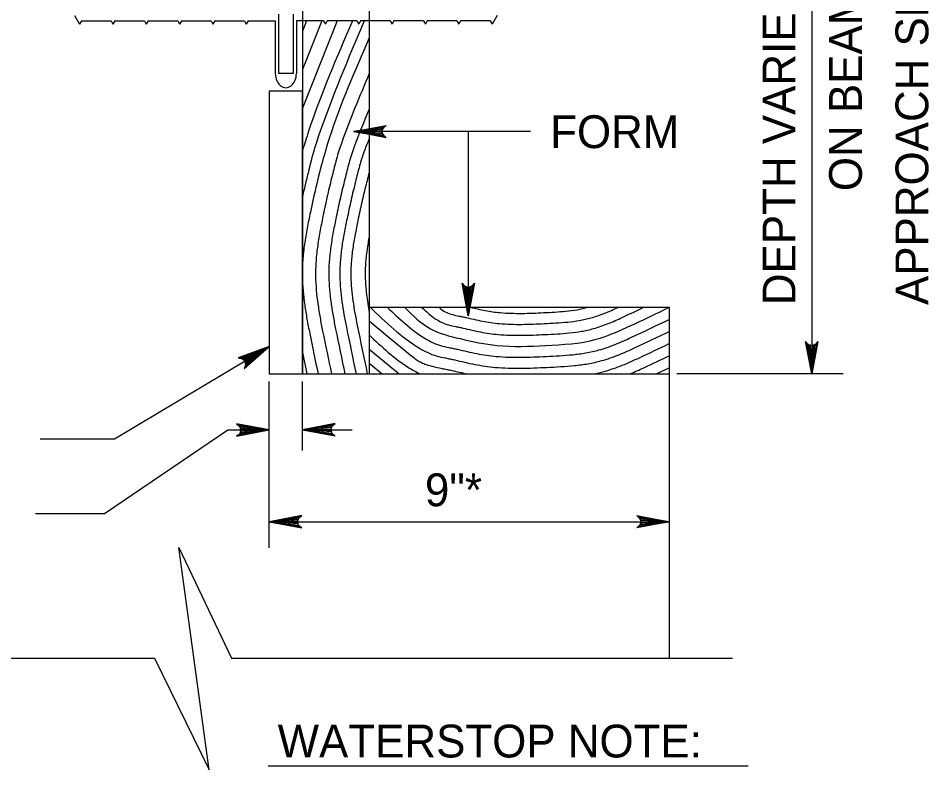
# Model space of a CAD drawing. Extents: x 636530 to 644067, y 294168 to 299122.
# Drawn here: x 636586.8 to 636670, y 298165.7 to 298234.3 of the extents above; entities that cross this region are included whole.
import ezdxf

# ---------------------------------------------------------------- set-up
doc = ezdxf.new("R2010")
doc.units = 0
doc.layers.add('1', color=7, linetype='Continuous')

msp = doc.modelspace()

# ---------------------------------------------------------------- linework, layer by layer
at = {"layer": '1'}
for p, q in [((636618.88, 298266.856), (636618.88, 298201.834)), ((636659.328, 298266.856), (636659.328, 298201.834)), ((636612.784, 298245.46), (636612.784, 298201.834)), ((636610.598, 298234.706), (636610.598, 298229.277)), ((636611.921, 298234.706), (636611.921, 298229.277)), ((636591.955, 298234.598), (636592.405, 298233.79)), ((636592.572, 298234.09), (636592.405, 298233.79)), ((636592.572, 298234.09), (636595.285, 298234.09)), ((636595.285, 298234.09), (636595.453, 298233.79)), ((636595.62, 298234.09), (636595.453, 298233.79)), ((636595.62, 298234.09), (636598.333, 298234.09)), ((636598.333, 298234.09), (636598.501, 298233.79)), ((636598.668, 298234.09), (636598.501, 298233.79)), ((636598.668, 298234.09), (636601.381, 298234.09)), ((636601.381, 298234.09), (636601.549, 298233.79)), ((636601.716, 298234.09), (636601.549, 298233.79)), ((636601.716, 298234.09), (636604.429, 298234.09)), ((636604.429, 298234.09), (636604.597, 298233.79)), ((636604.764, 298234.09), (636604.597, 298233.79)), ((636604.764, 298234.09), (636607.477, 298234.09)), ((636607.477, 298234.09), (636607.645, 298233.79)), ((636607.812, 298234.09), (636607.645, 298233.79)), ((636607.812, 298234.09), (636610.298, 298234.09)), ((636610.298, 298234.09), (636610.298, 298229.277)), ((636612.221, 298234.09), (636612.221, 298229.277)), ((636614.707, 298234.09), (636612.221, 298234.09)), ((636613.148, 298234.09), (636612.784, 298233.174)), ((636614.547, 298234.09), (636612.784, 298229.656)), ((636615.946, 298234.09), (636612.784, 298226.138)), ((636614.707, 298234.09), (636614.875, 298233.79)), ((636615.042, 298234.09), (636614.875, 298233.79)), ((636617.755, 298234.09), (636615.042, 298234.09)), ((636617.755, 298234.09), (636617.923, 298233.79)), ((636618.09, 298234.09), (636617.923, 298233.79)), ((636620.803, 298234.09), (636618.09, 298234.09)), ((636620.803, 298234.09), (636620.971, 298233.79)), ((636621.138, 298234.09), (636620.971, 298233.79)), ((636623.851, 298234.09), (636621.138, 298234.09)), ((636623.851, 298234.09), (636624.019, 298233.79)), ((636624.186, 298234.09), (636624.019, 298233.79)), ((636626.899, 298234.09), (636624.186, 298234.09)), ((636626.899, 298234.09), (636627.067, 298233.79)), ((636627.234, 298234.09), (636627.067, 298233.79)), ((636629.947, 298234.09), (636627.234, 298234.09)), ((636629.947, 298234.09), (636630.115, 298233.79)), ((636630.565, 298234.598), (636630.115, 298233.79)), ((636611.921, 298229.277), (636610.598, 298229.277)), ((636609.736, 298227.667), (636609.736, 298201.834)), ((636633.627, 298223.984), (636617.457, 298223.984)), ((636627.94, 298223.984), (636627.94, 298207.156)), ((636618.88, 298207.93), (636646.312, 298207.93)), ((636646.312, 298207.93), (636646.312, 298201.834)), ((636595.59, 298195.919), (636609.736, 298204.343)), ((636618.88, 298204.107), (636621.631, 298201.834)), ((636612.784, 298203.789), (636613.188, 298201.834)), ((636618.88, 298202.81), (636620.061, 298201.834)), ((636645.122, 298201.834), (636646.312, 298202.397)), ((636609.736, 298201.834), (636646.312, 298201.834)), ((636646.312, 298201.834), (636646.312, 298175.875)), ((636662.191, 298201.834), (636646.991, 298201.834)), ((636609.736, 298185.954), (636609.736, 298201.154)), ((636612.784, 298194.844), (636612.784, 298201.154)), ((636594.695, 298189.095), (636605.952, 298196.722)), ((636605.952, 298196.722), (636609.736, 298196.722)), ((636612.784, 298196.722), (636617.326, 298196.722)), ((636588.805, 298195.919), (636595.59, 298195.919)), ((636588.363, 298189.095), (636594.695, 298189.095)), ((636609.736, 298188.331), (636646.312, 298188.331)), ((636557.946, 298175.875), (636599.254, 298175.875)), ((636606.289, 298175.875), (636652.095, 298175.875)), ((636609.636, 298166.029), (636653.514, 298166.029))]:
    msp.add_line(p, q, dxfattribs=at)
msp.add_lwpolyline([(636609.736, 298201.834), (636612.784, 298201.834), (636612.784, 298227.667), (636609.736, 298227.667)], close=True, dxfattribs=at)
for points in [[(636617.457, 298223.984), (636620.44, 298224.543), (636620.325, 298224.463), (636620.21, 298224.384), (636620.151, 298224.284), (636620.092, 298224.184), (636620.074, 298224.084), (636620.057, 298223.984), (636620.074, 298223.884), (636620.092, 298223.784), (636620.151, 298223.684), (636620.21, 298223.584), (636620.325, 298223.504), (636620.44, 298223.424), (636617.457, 298223.984), (636620.325, 298223.504), (636620.21, 298223.584), (636617.457, 298223.984), (636620.151, 298223.684), (636620.092, 298223.784), (636617.457, 298223.984), (636620.074, 298223.884), (636620.057, 298223.984), (636617.457, 298223.984), (636620.074, 298224.084), (636620.092, 298224.184), (636617.457, 298223.984), (636620.151, 298224.284), (636620.21, 298224.384), (636617.457, 298223.984), (636620.325, 298224.463)], [(636627.94, 298207.156), (636627.381, 298210.138), (636627.461, 298210.024), (636627.54, 298209.909), (636627.64, 298209.849), (636627.74, 298209.79), (636627.84, 298209.773), (636627.94, 298209.756), (636628.04, 298209.773), (636628.14, 298209.79), (636628.24, 298209.849), (636628.34, 298209.909), (636628.42, 298210.024), (636628.5, 298210.138), (636627.94, 298207.156), (636628.42, 298210.024), (636628.34, 298209.909), (636627.94, 298207.156), (636628.24, 298209.849), (636628.14, 298209.79), (636627.94, 298207.156), (636628.04, 298209.773), (636627.94, 298209.756), (636627.94, 298207.156), (636627.84, 298209.773), (636627.74, 298209.79), (636627.94, 298207.156), (636627.64, 298209.849), (636627.54, 298209.909), (636627.94, 298207.156), (636627.461, 298210.024)], [(636659.328, 298201.834), (636658.769, 298204.816), (636658.848, 298204.701), (636658.928, 298204.587), (636659.028, 298204.527), (636659.128, 298204.468), (636659.228, 298204.451), (636659.328, 298204.434), (636659.428, 298204.451), (636659.528, 298204.468), (636659.628, 298204.527), (636659.728, 298204.587), (636659.808, 298204.701), (636659.887, 298204.816), (636659.328, 298201.834), (636659.808, 298204.701), (636659.728, 298204.587), (636659.328, 298201.834), (636659.628, 298204.527), (636659.528, 298204.468), (636659.328, 298201.834), (636659.428, 298204.451), (636659.328, 298204.434), (636659.328, 298201.834), (636659.228, 298204.451), (636659.128, 298204.468), (636659.328, 298201.834), (636659.028, 298204.527), (636658.928, 298204.587), (636659.328, 298201.834), (636658.848, 298204.701)], [(636609.736, 298204.343), (636606.887, 298203.298), (636607.026, 298203.288), (636607.166, 298203.278), (636607.268, 298203.223), (636607.37, 298203.167), (636607.436, 298203.09), (636607.502, 298203.013), (636607.538, 298202.918), (636607.575, 298202.824), (636607.575, 298202.707), (636607.575, 298202.591), (636607.517, 298202.464), (636607.459, 298202.337), (636609.736, 298204.343), (636607.517, 298202.464), (636607.575, 298202.591), (636609.736, 298204.343), (636607.575, 298202.707), (636607.575, 298202.824), (636609.736, 298204.343), (636607.538, 298202.918), (636607.502, 298203.013), (636609.736, 298204.343), (636607.436, 298203.09), (636607.37, 298203.167), (636609.736, 298204.343), (636607.268, 298203.223), (636607.166, 298203.278), (636609.736, 298204.343), (636607.026, 298203.288)], [(636609.736, 298196.722), (636606.75, 298197.266), (636606.865, 298197.187), (636606.981, 298197.108), (636607.041, 298197.009), (636607.1, 298196.909), (636607.118, 298196.809), (636607.136, 298196.709), (636607.119, 298196.609), (636607.102, 298196.509), (636607.043, 298196.409), (636606.985, 298196.308), (636606.87, 298196.228), (636606.756, 298196.148), (636609.736, 298196.722), (636606.87, 298196.228), (636606.985, 298196.308), (636609.736, 298196.722), (636607.043, 298196.409), (636607.102, 298196.509), (636609.736, 298196.722), (636607.119, 298196.609), (636607.136, 298196.709), (636609.736, 298196.722), (636607.118, 298196.809), (636607.1, 298196.909), (636609.736, 298196.722), (636607.041, 298197.009), (636606.981, 298197.108), (636609.736, 298196.722), (636606.865, 298197.187)], [(636612.784, 298196.722), (636615.769, 298196.175), (636615.653, 298196.254), (636615.538, 298196.333), (636615.478, 298196.433), (636615.419, 298196.533), (636615.401, 298196.633), (636615.383, 298196.733), (636615.4, 298196.833), (636615.417, 298196.933), (636615.476, 298197.033), (636615.535, 298197.133), (636615.649, 298197.214), (636615.764, 298197.294), (636612.784, 298196.722), (636615.649, 298197.214), (636615.535, 298197.133), (636612.784, 298196.722), (636615.476, 298197.033), (636615.417, 298196.933), (636612.784, 298196.722), (636615.4, 298196.833), (636615.383, 298196.733), (636612.784, 298196.722), (636615.401, 298196.633), (636615.419, 298196.533), (636612.784, 298196.722), (636615.478, 298196.433), (636615.538, 298196.333), (636612.784, 298196.722), (636615.653, 298196.254)], [(636609.736, 298188.331), (636612.718, 298187.772), (636612.603, 298187.852), (636612.488, 298187.931), (636612.429, 298188.031), (636612.37, 298188.131), (636612.353, 298188.231), (636612.336, 298188.331), (636612.353, 298188.431), (636612.37, 298188.531), (636612.429, 298188.631), (636612.488, 298188.731), (636612.603, 298188.811), (636612.718, 298188.89), (636609.736, 298188.331), (636612.603, 298188.811), (636612.488, 298188.731), (636609.736, 298188.331), (636612.429, 298188.631), (636612.37, 298188.531), (636609.736, 298188.331), (636612.353, 298188.431), (636612.336, 298188.331), (636609.736, 298188.331), (636612.353, 298188.231), (636612.37, 298188.131), (636609.736, 298188.331), (636612.429, 298188.031), (636612.488, 298187.931), (636609.736, 298188.331), (636612.603, 298187.852)], [(636646.312, 298188.331), (636643.329, 298187.772), (636643.444, 298187.852), (636643.559, 298187.931), (636643.618, 298188.031), (636643.677, 298188.131), (636643.694, 298188.231), (636643.712, 298188.331), (636643.694, 298188.431), (636643.677, 298188.531), (636643.618, 298188.631), (636643.559, 298188.731), (636643.444, 298188.811), (636643.329, 298188.89), (636646.312, 298188.331), (636643.444, 298188.811), (636643.559, 298188.731), (636646.312, 298188.331), (636643.618, 298188.631), (636643.677, 298188.531), (636646.312, 298188.331), (636643.694, 298188.431), (636643.712, 298188.331), (636646.312, 298188.331), (636643.694, 298188.231), (636643.677, 298188.131), (636646.312, 298188.331), (636643.618, 298188.031), (636643.559, 298187.931), (636646.312, 298188.331), (636643.444, 298187.852)], [(636599.254, 298175.875), (636604.252, 298165.663), (636601.491, 298185.961), (636606.289, 298175.875)]]:
    msp.add_lwpolyline(points, dxfattribs=at)
msp.add_ellipse((636611.26, 298229.277), major_axis=(0, 1.283), ratio=0.75, start_param=1.570796, end_param=4.712389, dxfattribs=at)
for points in [[(636617.345, 298234.09), (636613.338, 298224.015), (636612.784, 298222.273)], [(636618.421, 298234.09), (636614.285, 298223.691), (636613.776, 298222.11), (636613.365, 298220.497), (636613.063, 298219.276), (636612.784, 298218.051)], [(636618.88, 298232.537), (636615.233, 298223.367), (636614.333, 298220.246), (636613.499, 298216.61), (636613.208, 298215.146), (636612.966, 298213.681), (636612.808, 298212.216), (636612.771, 298211.484), (636612.768, 298210.752), (636612.985, 298208.14), (636613.191, 298206.838), (636613.441, 298205.545), (636614.209, 298201.834)], [(636618.88, 298229.289), (636616.369, 298222.978), (636615.886, 298221.478), (636615.689, 298220.712), (636615.495, 298219.946), (636615.275, 298219.065), (636615.069, 298218.183), (636614.683, 298216.401), (636614.402, 298214.99), (636614.169, 298213.578), (636614.016, 298212.166), (636613.981, 298211.46), (636613.977, 298210.755), (636614.186, 298208.241), (636614.385, 298206.988), (636614.625, 298205.744), (636615.435, 298201.834)], [(636618.88, 298226.042), (636617.506, 298222.589), (636617.037, 298221.133), (636616.845, 298220.389), (636616.658, 298219.645), (636616.443, 298218.787), (636616.242, 298217.928), (636616.051, 298217.064), (636615.866, 298216.192), (636615.596, 298214.834), (636615.371, 298213.475), (636615.225, 298212.116), (636615.19, 298211.436), (636615.184, 298211.097), (636615.187, 298210.757), (636615.388, 298208.342), (636615.579, 298207.138), (636615.81, 298205.943), (636616.66, 298201.834)], [(636618.88, 298223.336), (636618.453, 298222.265), (636617.996, 298220.845), (636617.809, 298220.12), (636617.626, 298219.395), (636617.416, 298218.556), (636617.22, 298217.716), (636617.032, 298216.871), (636616.852, 298216.018), (636616.591, 298214.704), (636616.373, 298213.389), (636616.231, 298212.074), (636616.198, 298211.417), (636616.193, 298211.088), (636616.195, 298210.759), (636616.389, 298208.427), (636616.573, 298207.263), (636616.797, 298206.109), (636617.682, 298201.834)], [(636618.88, 298220.268), (636618.773, 298219.851), (636618.595, 298219.144), (636618.39, 298218.324), (636618.197, 298217.503), (636618.014, 298216.678), (636617.838, 298215.844), (636617.585, 298214.573), (636617.376, 298213.303), (636617.238, 298212.032), (636617.206, 298211.397), (636617.201, 298211.079), (636617.203, 298210.762), (636617.39, 298208.511), (636617.568, 298207.388), (636617.783, 298206.274), (636618.703, 298201.834)], [(636618.88, 298214.409), (636618.879, 298214.404), (636618.678, 298213.191), (636618.547, 298211.978), (636618.516, 298211.371), (636618.514, 298210.764), (636618.63, 298209.105), (636618.742, 298208.276), (636618.88, 298207.449)], [(636618.962, 298207.93), (636623.491, 298204.188), (636625.004, 298203.482), (636625.85, 298203.295), (636626.275, 298203.21), (636626.693, 298203.12), (636627.617, 298202.907), (636628.541, 298202.711), (636629.469, 298202.55), (636630.405, 298202.439), (636631.582, 298202.371), (636632.762, 298202.358), (636633.942, 298202.386), (636635.12, 298202.439), (636636.379, 298202.506), (636637.635, 298202.603), (636638.885, 298202.771), (636639.508, 298202.894), (636640.127, 298203.05), (636641.695, 298203.584), (636643.199, 298204.242), (636646.312, 298205.717)], [(636620.532, 298207.93), (636623.985, 298205.078), (636625.382, 298204.425), (636626.163, 298204.252), (636626.556, 298204.174), (636626.943, 298204.091), (636627.827, 298203.887), (636628.712, 298203.7), (636629.6, 298203.545), (636630.496, 298203.439), (636631.635, 298203.373), (636632.777, 298203.361), (636633.919, 298203.387), (636635.059, 298203.439), (636636.272, 298203.503), (636637.482, 298203.597), (636638.686, 298203.758), (636639.285, 298203.877), (636639.882, 298204.027), (636641.373, 298204.535), (636642.804, 298205.161), (636646.312, 298206.823)], [(636622.102, 298207.93), (636624.478, 298205.967), (636627.193, 298205.062), (636630.587, 298204.439), (636634.998, 298204.439), (636639.637, 298205.005), (636642.408, 298206.081), (636646.312, 298207.93)], [(636623.672, 298207.93), (636624.971, 298206.857), (636626.139, 298206.312), (636626.791, 298206.168), (636627.119, 298206.102), (636627.443, 298206.032), (636628.248, 298205.847), (636629.053, 298205.676), (636629.862, 298205.536), (636630.678, 298205.439), (636631.741, 298205.378), (636632.807, 298205.366), (636633.873, 298205.391), (636634.938, 298205.439), (636636.057, 298205.498), (636637.175, 298205.585), (636638.287, 298205.734), (636638.84, 298205.843), (636639.391, 298205.982), (636640.729, 298206.438), (636641.375, 298206.708), (636642.013, 298207), (636643.976, 298207.93)], [(636625.243, 298207.93), (636625.464, 298207.747), (636626.517, 298207.255), (636627.105, 298207.125), (636627.401, 298207.066), (636627.692, 298207.003), (636628.458, 298206.827), (636629.224, 298206.665), (636629.993, 298206.531), (636630.769, 298206.439), (636631.794, 298206.38), (636632.822, 298206.369), (636633.85, 298206.392), (636634.877, 298206.439), (636635.95, 298206.496), (636637.021, 298206.579), (636638.087, 298206.722), (636638.618, 298206.827), (636639.146, 298206.96), (636640.407, 298207.389), (636641.016, 298207.644), (636641.617, 298207.919), (636641.64, 298207.93)], [(636628.132, 298207.93), (636628.811, 298207.775), (636629.49, 298207.635), (636630.172, 298207.519), (636630.86, 298207.439), (636631.847, 298207.382), (636632.837, 298207.371), (636633.827, 298207.394), (636634.816, 298207.439), (636635.843, 298207.493), (636636.868, 298207.573), (636637.888, 298207.709), (636638.395, 298207.81), (636638.874, 298207.93)], [(636618.88, 298206.701), (636622.998, 298203.298), (636623.176, 298203.163), (636623.364, 298203.041), (636623.56, 298202.931), (636623.763, 298202.833), (636624.189, 298202.664), (636624.626, 298202.539), (636625.536, 298202.337), (636625.993, 298202.246), (636626.444, 298202.149), (636627.83, 298201.834)], [(636618.88, 298205.404), (636622.505, 298202.409), (636623.506, 298201.834)], [(636639.362, 298201.834), (636639.869, 298201.944), (636640.121, 298202.006), (636640.372, 298202.072), (636640.791, 298202.195), (636641.206, 298202.333), (636642.016, 298202.632), (636642.811, 298202.964), (636643.595, 298203.323), (636646.312, 298204.61)], [(636642.715, 298201.834), (636643.99, 298202.404), (636646.312, 298203.504)]]:
    msp.add_spline(points, degree=3, dxfattribs=at)

# ---------------------------------------------------------------- texts
for s, p in [('APPROACH SLAB TYPE', (636669.989, 298208.136)), ('DEPTH VARIES BASED', (636657.845, 298208.124)), ('ON BEAM AND', (636663.917, 298218.542))]:
    msp.add_text(s, height=3, rotation=90, dxfattribs=at).set_placement(p)
for s, p in [('FORM', (636635.423, 298222.474)), ('9"*', (636623.972, 298189.746)), ('WATERSTOP NOTE:', (636610.509, 298166.788))]:
    msp.add_text(s, height=3, dxfattribs=at).set_placement(p)

doc.saveas('drawing.dxf')
